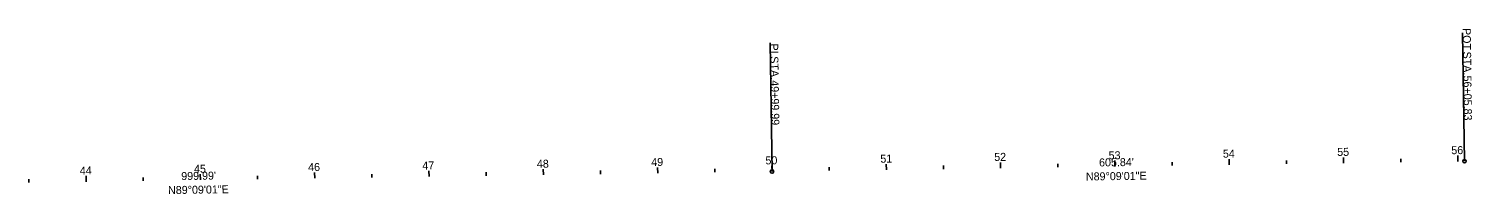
# Model space of a CAD drawing. Extents: x 1805035 to 1810276, y 297762 to 303660.
# Drawn here: x 1809014 to 1810276, y 298369 to 298514 of the extents above; entities that cross this region are included whole.
import ezdxf

# ---------------------------------------------------------------- set-up
doc = ezdxf.new("R2010")
doc.units = 0
for name, color, linetype in [('GE_P_Alignment_100_Bearings', 7, 'Continuous'), ('GE_P_Alignment_100_Cardinal_Points', 7, 'Continuous'), ('GE_P_Alignment_100_Distances', 7, 'Continuous'), ('GE_P_Alignment_100_Stations', 7, 'Continuous')]:
    doc.layers.add(name, color=color, linetype=linetype)

msp = doc.modelspace()

# ---------------------------------------------------------------- linework, layer by layer
at = {"layer": 'GE_P_Alignment_100_Cardinal_Points'}
for p, q in [((1810269.7, 298397.8), (1810268.1, 298510.3)), ((1809664, 298388.8), (1809662.3, 298501.3))]:
    msp.add_line(p, q, dxfattribs=at)
for centre in [(1810269.7, 298397.8), (1809664, 298388.8)]:
    msp.add_circle(centre, 1.5, dxfattribs=at)
at = {"layer": 'GE_P_Alignment_100_Stations'}
for p, q in [((1809464, 298385.9), (1809463.9, 298390.9)), ((1809564, 298387.3), (1809563.9, 298392.3)), ((1809614, 298388.1), (1809613.9, 298391.1)), ((1809664, 298388.8), (1809663.9, 298393.8)), ((1809714, 298389.6), (1809713.9, 298392.6)), ((1809764, 298390.3), (1809763.9, 298395.3)), ((1809814, 298391), (1809813.9, 298394)), ((1809863.9, 298391.8), (1809863.9, 298396.8)), ((1809913.9, 298392.5), (1809913.9, 298395.5)), ((1809963.9, 298393.3), (1809963.9, 298398.3)), ((1810013.9, 298394), (1810013.9, 298397)), ((1810063.9, 298394.7), (1810063.8, 298399.7)), ((1810113.9, 298395.5), (1810113.9, 298398.5)), ((1810163.9, 298396.2), (1810163.8, 298401.2)), ((1810213.9, 298397), (1810213.9, 298400)), ((1810263.9, 298397.7), (1810263.8, 298402.7)), ((1809014, 298379.2), (1809014, 298382.2)), ((1809064, 298379.9), (1809064, 298384.9)), ((1809114, 298380.7), (1809114, 298383.7)), ((1809164, 298381.4), (1809163.9, 298386.4)), ((1809214, 298382.1), (1809214, 298385.1)), ((1809264, 298382.9), (1809263.9, 298387.9)), ((1809314, 298383.6), (1809314, 298386.6)), ((1809364, 298384.4), (1809363.9, 298389.4)), ((1809414, 298385.1), (1809413.9, 298388.1)), ((1809514, 298386.6), (1809513.9, 298389.6))]:
    msp.add_line(p, q, dxfattribs=at)

# ---------------------------------------------------------------- texts
at = {"layer": 'GE_P_Alignment_100_Bearings'}
for rotation, p in [(0.8497, (1809938.6, 298380.9)), (0.8496, (1809135.8, 298369))]:
    msp.add_text('N89°09\'01"E', height=7, rotation=rotation, dxfattribs=at).set_placement(p)
at = {"layer": 'GE_P_Alignment_100_Cardinal_Points'}
for s, p in [('POT', (1810268.1, 298514.3)), ('PI', (1809662.4, 298500.7)), (' STA. ', (1810268.4, 298496.3)), (' STA. ', (1809662.5, 298492.2)), ('49+99.99', (1809662.9, 298468.6)), ('56+05.83', (1810268.7, 298472.7))]:
    msp.add_text(s, height=7, rotation=270.8497, dxfattribs=at).set_placement(p)
at = {"layer": 'GE_P_Alignment_100_Distances'}
for s, rotation, p in [("605.84'", 0.8497, (1809950.1, 298393.2)), ("999.99'", 0.8496, (1809147.3, 298381.3))]:
    msp.add_text(s, height=7, rotation=rotation, dxfattribs=at).set_placement(p)
at = {"layer": 'GE_P_Alignment_100_Stations'}
for s, rotation, p in [('51', 0.8497, (1809758.8, 298396.5)), ('52', 0.8497, (1809858.4, 298398)), ('53', 0.8497, (1809958.5, 298399.4)), ('54', 0.8497, (1810058.4, 298400.9)), ('55', 0.8497, (1810158.4, 298402.4)), ('56', 0.8497, (1810258.2, 298403.9)), ('44', 0.8496, (1809058.6, 298386.1)), ('45', 0.8496, (1809158.5, 298387.6)), ('46', 0.8496, (1809258.3, 298389.1)), ('47', 0.8496, (1809358.2, 298390.5)), ('48', 0.8496, (1809458.4, 298392)), ('49', 0.8496, (1809558.4, 298393.5)), ('50', 0.8497, (1809658.3, 298395))]:
    msp.add_text(s, height=7, rotation=rotation, dxfattribs=at).set_placement(p)

doc.saveas('drawing.dxf')
